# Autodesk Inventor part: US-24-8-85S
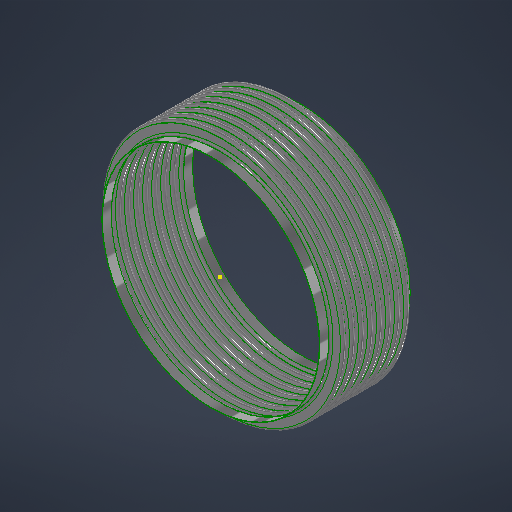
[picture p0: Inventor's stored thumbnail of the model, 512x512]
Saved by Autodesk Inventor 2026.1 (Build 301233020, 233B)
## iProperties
Category: 18 GA (0.048 THICK)
RuleStatus: InUse
Created: 2026-07
Part Number: US-24-8-85S
Project: =STOCK BELLOWS: <Stock Number><SFILL>
Material: ASTM A240-304
Description: =STOCK BELLOWS: <Stock Number>, <SID_> I.D., <SOD_> O.D., <SPLY_> PLY, <Category>, <SNET_CONS> CONS.<PITCH_><STANGENT_> TANGENT<SFILL>
Document SubType Name: Sheet Metal
Designer: LC
Stock Number: U.S-24-8-85S
Surface Area: 659.127 cm^2
Volume: 56.61 cm^3
Sheet Metal Rule: Default
Appearance: STAINLESS STEEL
NET_TUBE: 3.428
COUNTER: 1.500
PBAR: 1.214
PSET: 5.356
PLY: 2
CONS: 2
THK: 0.036
ID: 4.500
OD: 5.500
CONS_: 2
TANGENT: 0.500
PITCH: 0.375
BELLOWS_UPSET: 0.000
NET_CONS: 2
S_CONS: 0
Description_Units: 0
ID_M: 114.30 mm
OD_M: 139.70 mm
THK_M: 0.91 mm
ID_U: 4.500 in
OD_U: 5.500 in
THK_U: 0.036 in
TANGENT2: 0.500
d79: 1.000
d82: 1.000
d83: 26.000
d84: 24.000
d80: 2.571
d81: 10
SID: 2.375
SCONS_: 8
SPITCH: 0.250
SBELLOWS_UPSET: 0.000
SNET_CONS: 8
SS_CONS: 0
SCONS: 8
d174: 8
d177: 0.018
d178: 2.375
d179: 3.000
d180: 0.375
d181: 1.000
d182: 0.000
d190: 8
d191: 1
d192: 1
d193: 8
d194: 0
PART_NUMBER: U.S-24-8-85S
PRESSURE: 85
SIZE: 24.00
STANGENT_: 1.000
d214: 8
d217: 0.030
d218: 6.625
d219: 8.125
d220: 0.500
d221: 1.000
d222: 0.000
d230: 8
d231: 1
d232: 1
d233: 8
d234: 0
STANGENT: 4.000
SPLY_: 1
STHK_: 0.048
SID_: 24.000
SOD_: 26.750
SPITCH_: 1.000
STANGENT__: 1.000
SBELLOWS_UPSET_: 0.000
SDIFF_TAN: 1.000
TAN_TO_TAN: 0.750 in
d252: 2
d275: 2
d287: 0.050
d289: 0.500
d290: 0.000
d263: 2
d265: 1
d268: 2
d269: 0
d286: 2
d288: 1
d291: 2
d292: 0
SOD_NECK: 24 1/8
CFILL: .
SFILL: .
PITCH_: =, <SPITCH_> PITCH,
SREROLL: 0.750
MATTABLE: 20 GA (0.036 THICK)
MESH: ,
CSECT: 2
Author: LC
Keywords: 20 GA (0.036 THICK)
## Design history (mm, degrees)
sketch "Sketch2"
  geometry: L1 (0, -183.595)-(0, 600.956) reference; L2 (58.979, 0)-(57.15, 0); L3 (60.446, -1.467)-(66.554, -1.467); L4 (60.446, -3.296)-(66.554, -3.296); L5 (66.554, -8.058)-(60.446, -8.058); L6 (66.554, -6.229)-(60.446, -6.229); L7 (58.979, -9.525)-(57.15, -9.525); L8 (60.446, 0)-(60.446, -9.525); L9 (66.554, -4.762)-(69.85, -4.763); L10 (57.15, 0)-(57.15, -9.525); L11 (20.376, 102.841)-(20.376, 101.926); L12 (58.262, 488.877)-(58.262, 349.177); L13 (58.262, 479.352)-(58.262, 339.652); L14 (93.133, -58.817)-(93.133, -71.517); L15 (118.746, -66.401)-(118.746, -66.401); L16 (66.554, -6.229)-(66.554, -8.058); L17 (60.446, -6.229)-(60.446, -8.058); L18 (60.446, -7.144)-(66.554, -7.144); L19 (69.85, 0)-(69.85, -9.525); L20 (-66.554, -6.229)-(-66.554, -8.058); L21 (-66.554, -1.467)-(-60.446, -1.467); L22 (-66.554, -3.296)-(-60.446, -3.296); L23 (-60.446, -6.229)-(-66.554, -6.229); L24 (-66.554, -7.144)-(-60.446, -7.144); L25 (-60.446, -8.058)-(-66.554, -8.058); L26 (-60.446, -6.229)-(-60.446, -8.058); L27 (-57.15, -2.522)-(-57.15, -12.047); L28 (-60.446, -4.763)-(-57.15, -4.763); L29 (-66.554, 3.828)-(-66.554, -9.525); L30 (-68.021, 0)-(-69.85, 0); L31 (-69.85, 0)-(-69.85, -9.525); L32 (-68.021, -9.525)-(-69.85, -9.525); A1 r 1.467 centre (60.446, 0) between (58.979, 0) and (60.446, -1.467); A2 r 3.296 centre (60.446, 0) between (57.15, 0) and (60.446, -3.296); A3 r 3.296 centre (66.554, -4.762) between (66.554, -8.058) and (66.554, -1.467); A4 r 1.467 centre (66.554, -4.762) between (66.554, -6.229) and (66.554, -3.296); A5 r 1.467 centre (60.446, -9.525) between (60.446, -8.058) and (58.979, -9.525); A6 r 3.296 centre (60.446, -9.525) between (60.446, -6.229) and (57.15, -9.525); A7 r 2.381 centre (66.554, -4.762) between (66.554, -7.144) and (68.936, -4.762); A8 r 2.381 centre (60.446, -9.525) between (60.446, -7.144) and (58.064, -9.525); A9 r 1.467 centre (-66.554, -9.525) between (-66.554, -8.058) and (-68.021, -9.525); A10 r 1.467 centre (-60.446, -4.763) between (-60.446, -6.229) and (-60.446, -3.296); A11 r 2.381 centre (-60.446, -4.763) between (-60.446, -7.144) and (-58.064, -4.763); A12 r 3.296 centre (-60.446, -4.763) between (-60.446, -8.058) and (-60.446, -1.467); A13 r 2.381 centre (-66.554, -9.525) between (-66.554, -7.144) and (-68.936, -9.525); A14 r 3.296 centre (-66.554, -9.525) between (-66.554, -6.229) and (-69.85, -9.525); A15 r 1.467 centre (-66.554, 0) between (-68.021, 0) and (-66.554, -1.467); A16 r 3.296 centre (-66.554, 0) between (-69.85, 0) and (-66.554, -3.296); 10 further points
  constraints: 62 end point, 38 point on circle, 20 tangent, 16 centre point, 12 parallel, 9 midpoint, 7 vertical, 6 coincident, 6 concentric, 6 point on line, 4 equal radius, 4 perpendicular, 3 horizontal, 1 collinear, 1 horizontal alignment, 10 other
  dimensions: "THK" = 0.9144 distance of L11.start L11.end; "ID" = 114.3 distance of L11.end point (20.376, -12.374); "OD" = 139.7 distance of L12.start L12.end; "PITCH" = 9.525 distance of L12.start L13.start; "TANGENT" = 12.7 distance of L14.start L14.end; "BELLOWS_UPSET" = 0 distance of L15.start L15.end; "d43" = 114.3 diameter of L10 L1 (= ID); "d44" = 139.7 diameter of L9.end L1 (= OD); "d45" = 1.8288 distance between parallel lines of L5 L6 (computed from THK, PLY); "d46" = 3.29565 radius of A3 (computed from PITCH, THK, PLY); "UPSET_PITCH" = 9.525 distance of L2.end L7.end (derived); "SIDEWALL_ANGLE" = 0 deg angle of L3 L9 (derived); "CON_GAP" = 2.9337 distance of point (60.446, -6.229) point (60.446, -3.296) (derived); "TAN1" = 3.74046 dimension on A8 (derived); "TAN2" = 3.74046 dimension on A7 (derived); "LEG1" = 6.1087 distance of L18.start L18.end (derived); "d278" = 1.8288 distance between parallel lines of L25 L23 (derived); "d279" = 3.29565 radius of A12 (derived); "d280" = 9.525 distance of L30.end L31.end (derived); "d281" = 360 deg dimension on L21 L28 (derived); "d282" = 2.9337 distance of point (-66.554, -6.229) point (-66.554, -3.296) (derived); "d283" = 3.74046 dimension on A13 (derived); "d284" = 3.74046 dimension on A11 (derived); "d285" = 6.1087 distance of L24.start L24.end (derived); "d293" = 114.3 diameter of L27 L1 (derived); "d294" = 139.7 diameter of L31 L1 (derived)
  node "Sketch Rectangular Pattern1" dims "d31" = 25.4, "ID" = 114.3
  node "Sketch Rectangular Pattern2" dims "d39" = 25.4, "PITCH" = 9.525
revolve "CONS" stored, may be unused: angle "d48" = 90 deg
node "BELLOW MIDPLANE"
pattern_linear "Rectangular Pattern2" dims "d52" = 9.525 (= UPSET_PITCH)
sketch "Sketch5"
  geometry: C1 r 58.979 at (0, 0) reference; C2 r 57.15 at (0, 0) reference
extrude "TANGENT" new body sketch "Sketch5" distance "d53" = 12.7 (= TANGENT); taper "d54" = 0 deg
revolve "SAMETAN" stored, may be unused: angle "d65" = 90 deg
revolve "DIFFTAN" stored, may be unused: angle "d70" = 90 deg
sketch "Sketch9"
  geometry: L1 (58.391, 0)-(-58.391, 0) reference; L2 (0, -17.78)-(0, 17.78) reference; L3 (41.708, 0)-(-41.708, 0); L4 (41.708, -11.906)-(41.708, 11.906); L5 (29.008, -11.906)-(29.008, 11.906); L6 (15.418, 11.906)-(15.418, -11.906); L7 (-29.008, -11.906)-(-29.008, 11.906); L8 (-41.708, -11.906)-(-41.708, 11.906); L9 (40.914, -11.906)-(40.914, 11.906); L10 (41.708, -11.906)-(40.914, -11.906); L11 (41.708, 11.906)-(40.914, 11.906); L12 (15.815, 11.906)-(15.022, 11.906); L13 (15.022, 11.906)-(15.022, -11.906); L14 (15.022, -11.906)-(15.815, -11.906); L15 (15.815, -11.906)-(15.815, 11.906); L16 (-15.815, 11.906)-(-15.815, -11.906); L17 (-15.418, 11.906)-(-15.418, -11.906); L18 (-15.815, -11.906)-(-15.022, -11.906); L19 (-15.022, -11.906)-(-15.022, 11.906); L20 (-15.022, 11.906)-(-15.815, 11.906); L21 (-41.708, -11.906)-(-40.914, -11.906); L22 (-40.914, -11.906)-(-40.914, 11.906); L23 (-40.914, 11.906)-(-41.708, 11.906); L24 (-41.708, 11.906)-(-41.708, -11.906); L25 (41.708, -0.397)-(-41.708, -0.397); L26 (-41.708, -0.397)-(-41.708, 0.397); L27 (-41.708, 0.397)-(41.708, 0.397); L28 (41.708, 0.397)-(41.708, -0.397); L29 (-41.708, 11.906)-(41.708, 11.906); L30 (41.708, 11.906)-(41.708, 12.7); L31 (41.708, 12.7)-(-41.708, 12.7); L32 (-41.708, 12.7)-(-41.708, 11.906); L33 (41.708, -11.906)-(-41.708, -11.906); L34 (-41.708, -11.906)-(-41.708, -12.7); L35 (-41.708, -12.7)-(41.708, -12.7); L36 (41.708, -12.7)-(41.708, -11.906); 30 further points
  constraints: 68 end point, 13 midpoint, 13 parallel, 8 horizontal, 7 perpendicular, 6 equal length, 3 point on line, 2 vertical, 14 other
  dimensions: "d115" = 23.8125 distance of L4.start L4.end (derived); "d116" = 12.7 distance between parallel lines of L4 L5 (derived); "d117" = 13.58962 distance between parallel lines of L5 L6 (derived); "d125" = 44.42645 distance between parallel lines of L7 L6 (derived); "d127" = 12.7 distance between parallel lines of L8 L7 (derived); "d128" = 26.28962 distance between parallel lines of L6 L4 (derived); "d130" = 83.41607 distance between parallel lines of L8 L4 (derived); "RULER_THK" = 0.79375 distance between parallel lines of L4 L9; "d135" = 0.79375 distance of L13.end L14.end (derived); "d138" = 30.83684 distance of L13.end L16.end (derived); "d143" = 0.79375 distance of L22.end L8.end (derived); "d144" = 0.79375 distance between parallel lines of L27 L25 (derived)
extrude "RULER" join sketch "Sketch9" distance "d149" = 0.79375 (derived); taper "d150" = 0 deg
extrude "BARS" join sketch "Sketch9" distance "d151" = 0.79375 (derived); taper "d152" = 0 deg
pattern_linear "Rectangular Pattern4" dims "d155" = 30.83684 (derived)
sketch "Sketch13"
  geometry: L1 (93.149, -52.467)-(93.149, -77.867); L2 (306.019, 0)-(304.8, 0); L3 (306.019, -25.4)-(304.8, -25.4); L4 (332.765, -19.66)-(311.76, -19.66); L5 (332.765, -18.44)-(311.76, -18.44); L6 (332.765, -12.7)-(339.725, -12.7); L7 (311.76, -5.74)-(332.765, -5.74); L8 (311.76, 0)-(311.76, -25.4); L9 (304.8, 0)-(304.8, -25.4); L10 (58.254, -167.289)-(58.254, -846.739); L11 (58.254, -192.689)-(58.254, -872.139); L12 (58.254, -243.489)-(58.254, -922.939); L13 (58.254, -268.889)-(58.254, -948.339); L14 (58.254, -294.289)-(58.254, -973.739); L15 (58.254, -319.689)-(58.254, -999.139); L16 (58.254, -345.089)-(58.254, -1024.539); L17 (58.254, -218.089)-(58.254, -897.539); L18 (20.376, 103.145)-(20.376, 101.926); L19 (311.76, -6.96)-(332.765, -6.96); L20 (0, -1209.436)-(0, 321.909) reference; L21 (-62.865, 0)-(377.19, 0) reference; A1 r 5.74 centre (311.76, 0) between (306.019, 0) and (311.76, -5.74); A2 r 5.74 centre (311.76, -25.4) between (311.76, -19.66) and (306.019, -25.4); A3 r 6.96 centre (311.76, -25.4) between (311.76, -18.44) and (304.8, -25.4); A4 r 5.74 centre (332.765, -12.7) between (332.765, -18.44) and (332.765, -6.96); A5 r 6.96 centre (332.765, -12.7) between (332.765, -19.66) and (332.765, -5.74); A6 r 6.96 centre (311.76, 0) between (304.8, 0) and (311.76, -6.96); 6 further points; 1 other entity
  constraints: 38 end point, 15 point on circle, 9 tangent, 6 centre point, 6 parallel, 5 vertical alignment, 4 point on line, 4 vertical, 3 coincident, 3 concentric, 2 collinear, 2 equal radius, 1 horizontal, 1 perpendicular, 23 other
  dimensions: "SBELLOWS_UPSET_" = 0 distance of point (118.762, -66.401) point (118.762, -66.401); "STOTAL_THK_BELLOW__" = 1.2192 distance between parallel lines of L4 L5 (derived); "d224" = 6.9596 radius of A5 (derived); "d225" = 25.4 distance of L2.end L3.end (derived); "SSIDEWALL_ANGLE_" = 0 deg angle of L7 L6 (derived); "SSCON_GAP_" = 11.4808 distance of point (311.76, -18.44) point (311.76, -6.96) (derived); "d235" = 609.6 diameter of L9 L20 (derived); "d236" = 679.45 diameter of L6.end L20 (derived)
  node "Sketch Rectangular Pattern4" dims "d228" = 25.4
  node "Sketch Rectangular Pattern5" dims "d229" = 25.4
revolve "SBELLOW" stored, may be unused: angle "d197" = 90 deg
pattern_linear "Rectangular Pattern5" dims "d204" = 25.4 (derived)
revolve "STANGENT" stored, may be unused: angle "d240" = 90 deg
revolve "SSAMETAN" stored, may be unused: angle "d241" = 90 deg
revolve "SDIFFTAN" stored, may be unused: angle "d246" = 90 deg
revolve "INVCON" stored, may be unused: angle "d295" = 90 deg
pattern_linear "Rectangular Pattern6" dims "d298" = 9.525 (derived)
revolve "INVTANGENT" stored, may be unused: angle "d302" = 90 deg
revolve "INVSAMETAN" stored, may be unused: angle "d307" = 90 deg
revolve "INVDIFFTAN" stored, may be unused: angle "d312" = 90 deg
sketch "ID BELLOW MOUNT CALC"
  geometry: L1 (44.45, 0)-(38.1, 0); L2 (38.1, 0)-(38.1, 12.7); L3 (38.1, 12.7)-(44.45, 12.7); L4 (44.45, 12.7)-(44.45, 0); L5 (36.513, 12.7)-(34.684, 12.7); L6 (34.684, 12.7)-(34.684, 0); L7 (34.684, 0)-(36.513, 0); L8 (36.513, 0)-(36.513, 12.7); L9 (0, -2.54)-(0, 15.24) reference; L10 (-8.89, 0)-(53.34, 0) reference; 1 further point
  constraints: 16 end point, 5 parallel, 2 collinear, 2 horizontal, 2 perpendicular
  dimensions: "d314" = 12.7 distance of L5.end L6.end (derived); "d315" = 1.8288 distance of L5.start L5.end (derived); "IG" = 1.5875 distance between parallel lines of L2 L8; "PIPE_OD" = 88.9 diameter of L4 L9; "PIPE_WALL" = 6.35 distance of L2.end L3.end; "ID_MT_BELLOW" = 69.3674 diameter of L6 L9 (derived)
revolve "CFILL" stored, may be unused: angle "d320" = 90 deg
pattern_linear "Rectangular Pattern7" dims "d323" = 9.525 (derived)
revolve "SFILL" stored, may be unused: angle "d324" = 90 deg
pattern_linear "Rectangular Pattern8" dims "d327" = 25.4 (derived)
node "STOCK BELLOW MIDPLANE"
sketch "Sketch21"
  geometry: L1 (0, -100.013)-(0, 100.013) reference; L2 (-100.013, 0)-(100.013, 0) reference; L3 (-0.099, 71.437)-(0.099, 71.437); L4 (0.099, 71.437)-(0.099, 55.562); L5 (0.099, 55.562)-(-0.099, 55.562); L6 (-0.099, 55.562)-(-0.099, 71.437); C1 r 55.562 at (0, 0); C2 r 71.437 at (0, 0); 3 further points
  constraints: 8 end point, 2 centre point, 2 coincident, 2 parallel, 2 tangent, 1 horizontal, 1 perpendicular, 1 other
  dimensions: "d329" = 111.125 diameter of C1 (derived); "d330" = 142.875 diameter of C2 (derived); "d331" = 0.19844 distance of L3.start L3.end
extrude "CLAMSHELL" cut sketch "Sketch21" extent not by distance; stored distance "d332" = 0; taper "d333" = 0 deg
pattern_circular "Circular Pattern1" dims angle "d335" = 180 deg (derived)
node "BELLOW"
sketch "Sketch6"
  geometry: L1 (-19.05, 58.979)-(-6.35, 58.979); L2 (-6.35, 58.979)-(-6.35, 57.15); L3 (-6.35, 57.15)-(-19.05, 57.15); L4 (-19.05, 57.15)-(-19.05, 58.979); L5 (2.54, 0)-(-59.69, 0) reference; L6 (-38.1, -108.388)-(-38.1, 156.601) reference; 1 further point
  constraints: 8 end point, 2 parallel, 1 horizontal, 1 perpendicular
  dimensions: "d61" = 12.7 distance of L2.end L3.end (derived); "d62" = 1.8288 distance of L1.end L2.end (derived); "d63" = 114.3 diameter of L3 L5 (derived); "d64" = 19.05 distance between parallel lines of L4 L6 (derived)
sketch "Sketch12"
  geometry: 1 further point
sketch "Sketch14"
  geometry: L1 (-25.4, 306.019)-(0, 306.019); L2 (0, 306.019)-(0, 304.8); L3 (0, 304.8)-(-25.4, 304.8); L4 (-25.4, 304.8)-(-25.4, 306.019); L5 (5.08, 0)-(-30.48, 0) reference; L6 (0, -56.124)-(0, 336.743) reference; 1 further point
  constraints: 8 end point, 2 parallel, 1 collinear, 1 horizontal, 1 perpendicular
  dimensions: "d237" = 1.2192 distance of L3.end L1.start (derived); "d238" = 609.6 diameter of L3 L5 (derived); "d239" = 25.4 distance of L1.start L1.end (derived); "SOD_NECK" = 612.0384 diameter of L1 L5 (derived)
sketch "Sketch15"
  geometry: L1 (-56.124, 0)-(336.743, 0) reference; L2 (304.8, -203.2)-(306.019, -203.2); L3 (306.019, -203.2)-(306.019, -228.6); L4 (306.019, -228.6)-(304.8, -228.6); L5 (304.8, -228.6)-(304.8, -203.2); L6 (0, -276.86)-(0, 60.96) reference; 1 further point
  constraints: 8 end point, 2 parallel, 1 horizontal, 1 perpendicular
  dimensions: "d205" = 25.4 distance of L4.end L2.start (derived); "d206" = 1.2192 distance of L3.end L4.end (derived); "d207" = 609.6 diameter of L5 L6 (derived); "d208" = 203.2 distance between parallel lines of L1 L2 (derived)
node "TANGENT_"
node "SAME_TAN"
sketch "Sketch8"
  geometry: L1 (58.979, -19.05)-(57.15, -19.05); L2 (57.15, -19.05)-(57.15, -31.75); L3 (57.15, -31.75)-(58.979, -31.75); L4 (58.979, -31.75)-(58.979, -19.05); L5 (0, -40.64)-(0, 21.59) reference; L6 (-108.388, 0)-(156.601, 0) reference; 1 further point
  constraints: 8 end point, 2 parallel, 1 horizontal, 1 perpendicular
  dimensions: "d66" = 114.3 diameter of L2 L5 (derived); "TOTAL_THK_BELLOW" = 1.8288 distance of L2.end L3.end (derived); "d68" = 19.05 distance between parallel lines of L1 L6 (derived); "d69" = 12.7 distance of L1.end L2.end (derived)
node "DIFF_TAN"
node "Sketch Rectangular Pattern3" dims "d138" = 30.83684 (derived), "d141" = 25.4
node "SBELLOW_"
node "STANGENT_"
node "SSAME_TAN"
sketch "Sketch16"
  geometry: L1 (306.019, -203.2)-(304.8, -203.2); L2 (304.8, -203.2)-(304.8, -228.6); L3 (304.8, -228.6)-(306.019, -228.6); L4 (306.019, -228.6)-(306.019, -203.2); L5 (0, -276.86)-(0, 60.96) reference; L6 (-56.124, 0)-(336.743, 0) reference; 1 further point
  constraints: 8 end point, 2 parallel, 1 horizontal, 1 perpendicular
  dimensions: "SDIFF_TAN" = 25.4 distance of L3.end L1.start; "d243" = 1.2192 distance of L2.end L3.end (derived); "d244" = 203.2 distance between parallel lines of L1 L6 (derived); "d245" = 609.6 diameter of L2 L5 (derived)
node "SDIFF_TAN"
body "Solid15"
sketch "Sketch17"
  geometry: L1 (69.85, 12.7)-(68.021, 12.7); L2 (68.021, 12.7)-(68.021, 0); L3 (68.021, 0)-(69.85, 0); L4 (69.85, 0)-(69.85, 12.7); L5 (0, -2.54)-(0, 15.24) reference; L6 (-13.97, 0)-(83.82, 0) reference; 2 further points
  constraints: 8 end point, 2 parallel, 1 horizontal, 1 midpoint, 1 perpendicular, 1 point on line
  dimensions: "INVTANGENT" = 12.7 distance of L3.end L1.start (derived); "d300" = 1.8288 distance of L1.start L1.end (derived); "d301" = 139.7 diameter of L4 L5 (derived)
body "Solid16"
sketch "Sketch18"
  geometry: L1 (69.85, -19.05)-(68.021, -19.05); L2 (68.021, -19.05)-(68.021, -31.75); L3 (68.021, -31.75)-(69.85, -31.75); L4 (69.85, -31.75)-(69.85, -19.05); L5 (-13.97, 0)-(83.82, 0) reference; L6 (0, -40.64)-(0, 21.59) reference; 1 further point
  constraints: 8 end point, 2 parallel, 1 horizontal, 1 perpendicular
  dimensions: "d303" = 19.05 distance between parallel lines of L1 L5 (derived); "d304" = 12.7 distance of L3.end L1.start (derived); "d305" = 1.8288 distance of L2.end L3.end (derived); "d306" = 139.7 diameter of L4 L6 (derived)
body "Solid17"
sketch "Sketch19"
  geometry: L1 (69.85, -19.05)-(68.021, -19.05); L2 (68.021, -19.05)-(68.021, -31.75); L3 (68.021, -31.75)-(69.85, -31.75); L4 (69.85, -31.75)-(69.85, -19.05); L5 (0, -40.64)-(0, 21.59) reference; L6 (-13.97, 0)-(83.82, 0) reference; 1 further point
  constraints: 8 end point, 2 parallel, 1 horizontal, 1 perpendicular
  dimensions: "d308" = 12.7 distance of L1.end L2.end (derived); "d309" = 139.7 diameter of L4 L5 (derived); "d310" = 1.8288 distance of L2.end L3.end (derived); "d311" = 19.05 distance between parallel lines of L1 L6 (derived)
body "Solid18"
body "Solid19"
body "Solid20"
other parameters: "BMPL" = -101.6, "PSET" = 136.0424 (computed from OD, THK, PLY) [user parameter], "PBAR" = 30.83684 (= 0.570796 x PITCH + OD - ID) [user parameter; used in 1 equation term], "COUNTER" = 15 [user parameter], "NET_TUBE" = 87.07367 (computed from CONS_, PBAR, TANGENT) [user parameter], "S_CONS" = 0 [user parameter; used in 1 equation term], "ID_M" = 114.3 (= ID) [user parameter], "OD_M" = 139.7 (= OD) [user parameter], "THK_M" = 0.9144 (= THK) [user parameter], "ID_U" = 114.3 (= ID) [user parameter], "OD_U" = 139.7 (= OD) [user parameter], "THK_U" = 0.9144 (= THK) [user parameter], "D_UNITS" = 0 [user parameter], "TANGENT2" = 12.7 [user parameter], "TAN_TO_TAN" = 19.05 [user parameter], "OD_NECK" = 117.9576 [user parameter], "d79" = 25.4, "d80" = 65.29823 [user parameter], "d82" = 25.4, "d83" = 660.4, "d84" = 609.6, "sa_0" = 4, "FRAME_THK" = 0.79375 [user parameter], "CON_FLAT" = 13.58962 [user parameter], "SID" = 60.325 [user parameter], "SPITCH" = 6.35 [user parameter], "STANGENT_" = 25.4 [user parameter], "SBELLOWS_UPSET" = 0 [user parameter], "SS_CONS" = 0 [user parameter], "STAN_TO_TAN_" = 203.2 [user parameter], "d100" = 1.2192 [user parameter], "d191" = 25.4 [user parameter], "d194" = 0 [user parameter], "STANGENT" = 101.6 [user parameter], "d234" = 0 [user parameter], "SUPSET_PITCH_" = 25.4 [user parameter], "d269" = 0 [user parameter], "d287" = 1.27, "d289" = 12.7, "d290" = 0, "d292" = 0 [user parameter], "Thickness" = 3.048 (derived), "KFactor" = 4.4, "BendRadius" = 3.048 (derived), "BendReliefWidth" = 3.048 (derived), "BendReliefDepth" = 1.524 (derived), "CornerReliefSize" = 12.192 (derived), "SeamGap" = 0.00508, "MinimumRemnant" = 6.096 (derived), "TransitionRadius" = 3.048 (derived), "JacobiRadiusSize" = 3.048 (derived), "GapSize" = 3.048 (derived), "SREROLL" = 19.05 [user parameter], "CUR_STK_PITCH" = 25.4 [user parameter], "d328" = -101.6 (derived), "CSECTDEG" = 180 deg [user parameter]
